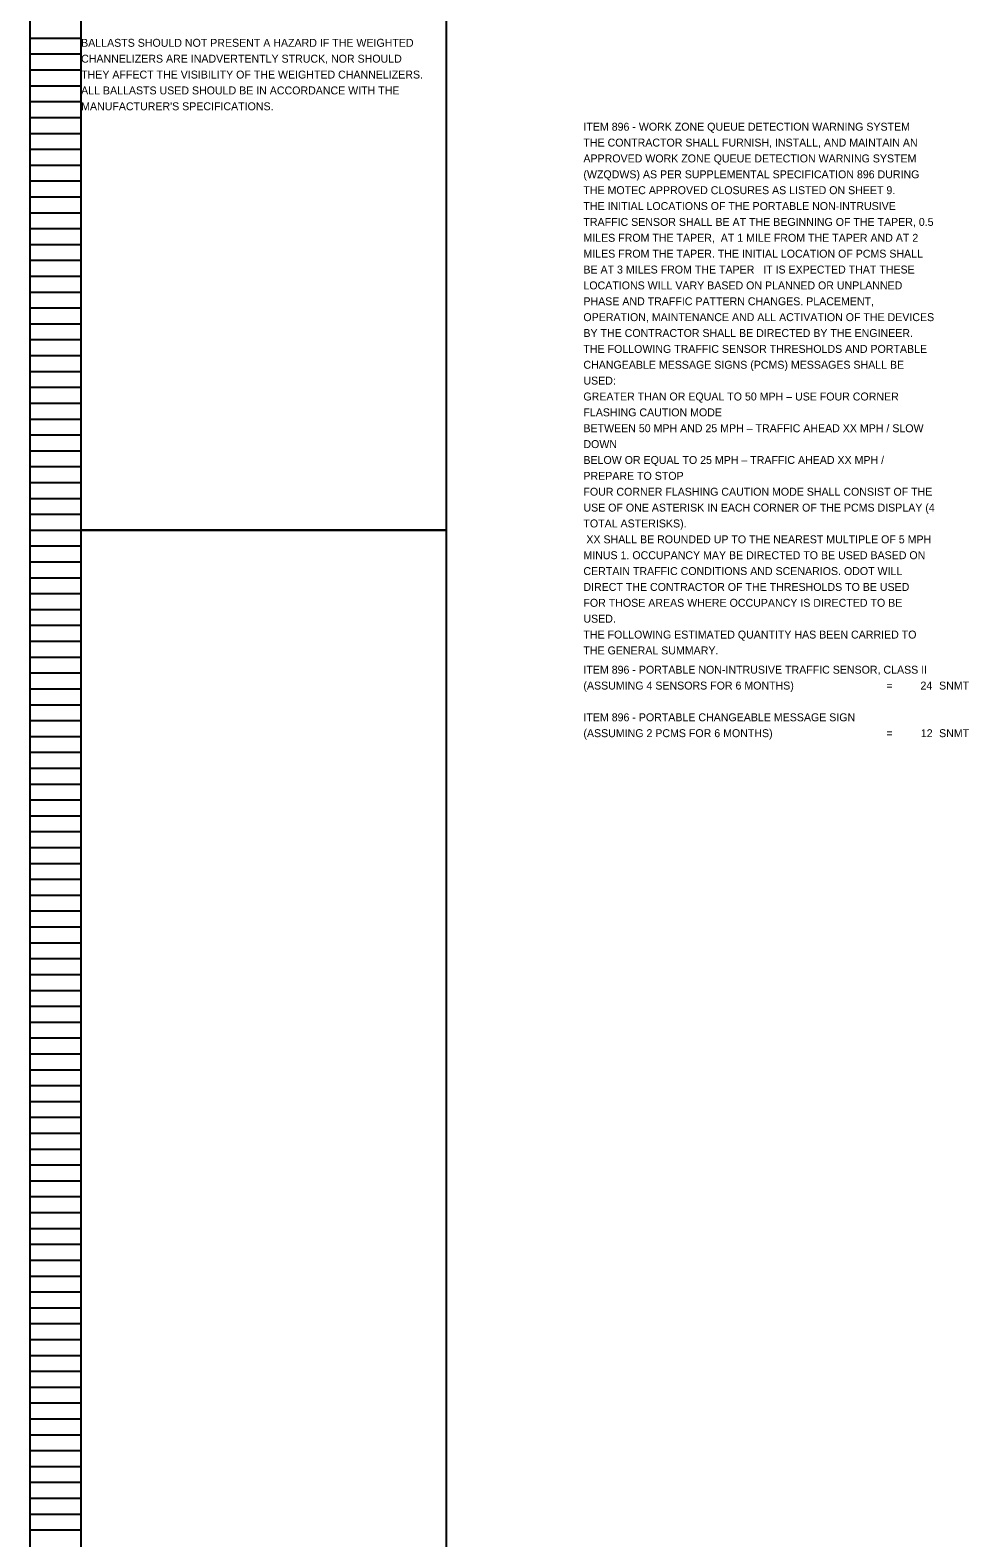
# Model space of a CAD drawing. Extents: x 16463 to 16500, y 5400 to 5823.
# Drawn here: x 16463.05 to 16479.61, y 5664.57 to 5691.17 of the extents above; entities that cross this region are included whole.
import ezdxf

# ---------------------------------------------------------------- set-up
doc = ezdxf.new("R2010")
doc.units = 0
for name, color, linetype in [('Default', 7, 'Continuous'), ('SC_Scratch1', 7, 'Continuous'), ('SH_Data', 7, 'Continuous')]:
    doc.layers.add(name, color=color, linetype=linetype)

msp = doc.modelspace()

# ---------------------------------------------------------------- linework, layer by layer
at = {"layer": 'SC_Scratch1'}
for points in [[(16463.949, 5702.512), (16470.389, 5702.512), (16470.389, 5682.352), (16463.949, 5682.352)], [(16463.949, 5682.352), (16470.389, 5682.352), (16470.389, 5662.192), (16463.949, 5662.192)]]:
    msp.add_lwpolyline(points, close=True, dxfattribs=at)
at = {"layer": 'SH_Data'}
for p, q in [((16463.049, 5682.352), (16463.049, 5702.512)), ((16463.949, 5682.352), (16463.949, 5702.512)), ((16463.049, 5691.032), (16463.949, 5691.032)), ((16463.049, 5690.752), (16463.949, 5690.752)), ((16463.049, 5690.472), (16463.949, 5690.472)), ((16463.049, 5690.192), (16463.949, 5690.192)), ((16463.049, 5689.912), (16463.949, 5689.912)), ((16463.049, 5689.632), (16463.949, 5689.632)), ((16463.049, 5689.352), (16463.949, 5689.352)), ((16463.049, 5689.072), (16463.949, 5689.072)), ((16463.049, 5688.792), (16463.949, 5688.792)), ((16463.049, 5688.512), (16463.949, 5688.512)), ((16463.049, 5688.232), (16463.949, 5688.232)), ((16463.049, 5687.952), (16463.949, 5687.952)), ((16463.049, 5687.672), (16463.949, 5687.672)), ((16463.049, 5687.392), (16463.949, 5687.392)), ((16463.049, 5687.112), (16463.949, 5687.112)), ((16463.049, 5686.832), (16463.949, 5686.832)), ((16463.049, 5686.552), (16463.949, 5686.552)), ((16463.049, 5686.272), (16463.949, 5686.272)), ((16463.049, 5685.992), (16463.949, 5685.992)), ((16463.049, 5685.712), (16463.949, 5685.712)), ((16463.049, 5685.432), (16463.949, 5685.432)), ((16463.049, 5685.152), (16463.949, 5685.152)), ((16463.049, 5684.872), (16463.949, 5684.872)), ((16463.049, 5684.592), (16463.949, 5684.592)), ((16463.049, 5684.312), (16463.949, 5684.312)), ((16463.049, 5684.032), (16463.949, 5684.032)), ((16463.049, 5683.752), (16463.949, 5683.752)), ((16463.049, 5683.472), (16463.949, 5683.472)), ((16463.049, 5683.192), (16463.949, 5683.192)), ((16463.049, 5682.912), (16463.949, 5682.912)), ((16463.049, 5682.632), (16463.949, 5682.632)), ((16463.049, 5662.192), (16463.049, 5682.352)), ((16463.049, 5682.352), (16463.949, 5682.352)), ((16463.049, 5682.352), (16463.949, 5682.352)), ((16463.949, 5662.192), (16463.949, 5682.352)), ((16463.049, 5682.072), (16463.949, 5682.072)), ((16463.049, 5681.792), (16463.949, 5681.792)), ((16463.049, 5681.512), (16463.949, 5681.512)), ((16463.049, 5681.232), (16463.949, 5681.232)), ((16463.049, 5680.952), (16463.949, 5680.952)), ((16463.049, 5680.672), (16463.949, 5680.672)), ((16463.049, 5680.392), (16463.949, 5680.392)), ((16463.049, 5680.112), (16463.949, 5680.112)), ((16463.049, 5679.832), (16463.949, 5679.832)), ((16463.049, 5679.552), (16463.949, 5679.552)), ((16463.049, 5679.272), (16463.949, 5679.272)), ((16463.049, 5678.992), (16463.949, 5678.992)), ((16463.049, 5678.712), (16463.949, 5678.712)), ((16463.049, 5678.432), (16463.949, 5678.432)), ((16463.049, 5678.152), (16463.949, 5678.152)), ((16463.049, 5677.872), (16463.949, 5677.872)), ((16463.049, 5677.592), (16463.949, 5677.592)), ((16463.049, 5677.312), (16463.949, 5677.312)), ((16463.049, 5677.032), (16463.949, 5677.032)), ((16463.049, 5676.752), (16463.949, 5676.752)), ((16463.049, 5676.472), (16463.949, 5676.472)), ((16463.049, 5676.192), (16463.949, 5676.192)), ((16463.049, 5675.912), (16463.949, 5675.912)), ((16463.049, 5675.632), (16463.949, 5675.632)), ((16463.049, 5675.352), (16463.949, 5675.352)), ((16463.049, 5675.072), (16463.949, 5675.072)), ((16463.049, 5674.792), (16463.949, 5674.792)), ((16463.049, 5674.512), (16463.949, 5674.512)), ((16463.049, 5674.232), (16463.949, 5674.232)), ((16463.049, 5673.952), (16463.949, 5673.952)), ((16463.049, 5673.672), (16463.949, 5673.672)), ((16463.049, 5673.392), (16463.949, 5673.392)), ((16463.049, 5673.112), (16463.949, 5673.112)), ((16463.049, 5672.832), (16463.949, 5672.832)), ((16463.049, 5672.552), (16463.949, 5672.552)), ((16463.049, 5672.272), (16463.949, 5672.272)), ((16463.049, 5671.992), (16463.949, 5671.992)), ((16463.049, 5671.712), (16463.949, 5671.712)), ((16463.049, 5671.432), (16463.949, 5671.432)), ((16463.049, 5671.152), (16463.949, 5671.152)), ((16463.049, 5670.872), (16463.949, 5670.872)), ((16463.049, 5670.592), (16463.949, 5670.592)), ((16463.049, 5670.312), (16463.949, 5670.312)), ((16463.049, 5670.032), (16463.949, 5670.032)), ((16463.049, 5669.752), (16463.949, 5669.752)), ((16463.049, 5669.472), (16463.949, 5669.472)), ((16463.049, 5669.192), (16463.949, 5669.192)), ((16463.049, 5668.912), (16463.949, 5668.912)), ((16463.049, 5668.632), (16463.949, 5668.632)), ((16463.049, 5668.352), (16463.949, 5668.352)), ((16463.049, 5668.072), (16463.949, 5668.072)), ((16463.049, 5667.792), (16463.949, 5667.792)), ((16463.049, 5667.512), (16463.949, 5667.512)), ((16463.049, 5667.232), (16463.949, 5667.232)), ((16463.049, 5666.952), (16463.949, 5666.952)), ((16463.049, 5666.672), (16463.949, 5666.672)), ((16463.049, 5666.392), (16463.949, 5666.392)), ((16463.049, 5666.112), (16463.949, 5666.112)), ((16463.049, 5665.832), (16463.949, 5665.832)), ((16463.049, 5665.552), (16463.949, 5665.552)), ((16463.049, 5665.272), (16463.949, 5665.272)), ((16463.049, 5664.992), (16463.949, 5664.992)), ((16463.049, 5664.712), (16463.949, 5664.712))]:
    msp.add_line(p, q, dxfattribs=at)

# ---------------------------------------------------------------- texts
at = {"layer": 'Default'}
for s, p in [('BALLASTS SHOULD NOT PRESENT A HAZARD IF THE WEIGHTED ', (16463.949, 5690.879)), ('CHANNELIZERS ARE INADVERTENTLY STRUCK, NOR SHOULD ', (16463.949, 5690.599)), ('THEY AFFECT THE VISIBILITY OF THE WEIGHTED CHANNELIZERS.  ', (16463.949, 5690.319)), ('ALL BALLASTS USED SHOULD BE IN ACCORDANCE WITH THE ', (16463.949, 5690.039)), ("MANUFACTURER'S SPECIFICATIONS.", (16463.949, 5689.759)), ('ITEM 896 - WORK ZONE QUEUE DETECTION WARNING SYSTEM ', (16472.813, 5689.399)), ('THE CONTRACTOR SHALL FURNISH, INSTALL, AND MAINTAIN AN ', (16472.813, 5689.119)), ('APPROVED WORK ZONE QUEUE DETECTION WARNING SYSTEM ', (16472.813, 5688.839)), ('(WZQDWS) AS PER SUPPLEMENTAL SPECIFICATION 896 DURING ', (16472.813, 5688.559)), ('THE MOTEC APPROVED CLOSURES AS LISTED ON SHEET 9.', (16472.813, 5688.279)), ('THE INITIAL LOCATIONS OF THE PORTABLE NON-INTRUSIVE ', (16472.813, 5687.999)), ('TRAFFIC SENSOR SHALL BE AT THE BEGINNING OF THE TAPER, 0.5 ', (16472.813, 5687.719)), ('MILES FROM THE TAPER,  AT 1 MILE FROM THE TAPER AND AT 2 ', (16472.813, 5687.439)), ('MILES FROM THE TAPER. THE INITIAL LOCATION OF PCMS SHALL ', (16472.813, 5687.159)), ('BE AT 3 MILES FROM THE TAPER   IT IS EXPECTED THAT THESE ', (16472.813, 5686.879)), ('LOCATIONS WILL VARY BASED ON PLANNED OR UNPLANNED ', (16472.813, 5686.599)), ('PHASE AND TRAFFIC PATTERN CHANGES. PLACEMENT, ', (16472.813, 5686.319)), ('OPERATION, MAINTENANCE AND ALL ACTIVATION OF THE DEVICES ', (16472.813, 5686.039)), ('BY THE CONTRACTOR SHALL BE DIRECTED BY THE ENGINEER.', (16472.813, 5685.759)), ('THE FOLLOWING TRAFFIC SENSOR THRESHOLDS AND PORTABLE ', (16472.813, 5685.479)), ('CHANGEABLE MESSAGE SIGNS (PCMS) MESSAGES SHALL BE ', (16472.813, 5685.199)), ('USED:', (16472.813, 5684.919)), ('GREATER THAN OR EQUAL TO 50 MPH – USE FOUR CORNER ', (16472.813, 5684.639)), ('FLASHING CAUTION MODE ', (16472.813, 5684.359)), ('BETWEEN 50 MPH AND 25 MPH – TRAFFIC AHEAD XX MPH / SLOW ', (16472.813, 5684.079)), ('DOWN ', (16472.813, 5683.799)), ('BELOW OR EQUAL TO 25 MPH – TRAFFIC AHEAD XX MPH / ', (16472.813, 5683.519)), ('PREPARE TO STOP ', (16472.813, 5683.239)), ('FOUR CORNER FLASHING CAUTION MODE SHALL CONSIST OF THE ', (16472.813, 5682.959)), ('USE OF ONE ASTERISK IN EACH CORNER OF THE PCMS DISPLAY (4 ', (16472.813, 5682.679)), ('TOTAL ASTERISKS).', (16472.813, 5682.399)), (' XX SHALL BE ROUNDED UP TO THE NEAREST MULTIPLE OF 5 MPH ', (16472.813, 5682.119)), ('MINUS 1. OCCUPANCY MAY BE DIRECTED TO BE USED BASED ON ', (16472.813, 5681.839)), ('CERTAIN TRAFFIC CONDITIONS AND SCENARIOS. ODOT WILL ', (16472.813, 5681.559)), ('DIRECT THE CONTRACTOR OF THE THRESHOLDS TO BE USED ', (16472.813, 5681.279)), ('FOR THOSE AREAS WHERE OCCUPANCY IS DIRECTED TO BE ', (16472.813, 5680.999)), ('USED. ', (16472.813, 5680.719)), ('THE FOLLOWING ESTIMATED QUANTITY HAS BEEN CARRIED TO ', (16472.813, 5680.439)), ('THE GENERAL SUMMARY.', (16472.813, 5680.159))]:
    msp.add_text(s, height=0.14, dxfattribs=at).set_placement(p)
at = {"layer": 'SC_Scratch1'}
for s, p in [('ITEM 896 - PORTABLE NON-INTRUSIVE TRAFFIC SENSOR, CLASS II', (16472.813, 5679.819)), ('(ASSUMING 4 SENSORS FOR 6 MONTHS)', (16472.813, 5679.539)), (' =', (16478.107, 5679.539)), ('24', (16478.761, 5679.539)), ('SNMT', (16479.089, 5679.539)), ('ITEM 896 - PORTABLE CHANGEABLE MESSAGE SIGN', (16472.813, 5678.979)), ('(ASSUMING 2 PCMS FOR 6 MONTHS)', (16472.813, 5678.699)), ('12', (16478.767, 5678.699)), ('SNMT', (16479.089, 5678.699)), (' =', (16478.107, 5678.699))]:
    msp.add_text(s, height=0.14, dxfattribs=at).set_placement(p)

doc.saveas('drawing.dxf')
